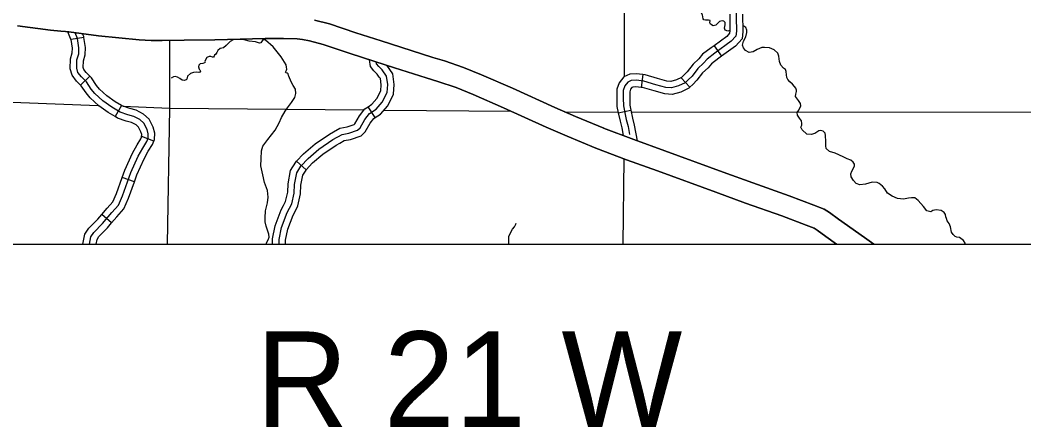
# Model space of a CAD drawing. Extents: x 1373862 to 1377080, y 1164775 to 1170415.
# Drawn here: x 1374841.3 to 1375030.3, y 1168559.4 to 1168636.1 of the extents above; entities that cross this region are included whole.
import ezdxf

# ---------------------------------------------------------------- set-up
doc = ezdxf.new("R2010")
doc.units = 0
for name, color, linetype in [('1', 7, 'Continuous'), ('Default', 7, 'Continuous'), ('Level 10', 7, 'Continuous'), ('Level 32', 7, 'Continuous'), ('Level 35', 7, 'Continuous'), ('Level 45', 7, 'Continuous'), ('Level 46', 7, 'Continuous'), ('Level 5', 7, 'Continuous')]:
    doc.layers.add(name, color=color, linetype=linetype)

msp = doc.modelspace()

# ---------------------------------------------------------------- linework, layer by layer
at = {"layer": '1'}
msp.add_lwpolyline([(1376107.39, 1169553.54), (1374750.71, 1169553.54), (1374750.71, 1168593.87), (1376107.39, 1168593.87)], close=True, dxfattribs=at)
at = {"layer": 'Level 10'}
msp.add_line((1374951.22, 1168615.68), (1374951.16, 1168615.71), dxfattribs=at)
for points in [[(1374896.71, 1168636.09), (1374899.53, 1168635.35), (1374904.52, 1168633.67), (1374909.28, 1168632.15), (1374913, 1168630.97), (1374918.97, 1168629.05), (1374921.19, 1168628.38), (1374924.8, 1168627.15), (1374928.16, 1168625.79), (1374933.97, 1168623.26), (1374942, 1168619.58), (1374945.85, 1168617.93), (1374951.22, 1168615.68)], [(1374951.22, 1168615.68), (1374945.85, 1168617.93), (1374942, 1168619.58), (1374933.97, 1168623.26), (1374928.16, 1168625.79), (1374924.8, 1168627.15), (1374921.19, 1168628.38), (1374918.97, 1168629.05), (1374913, 1168630.97), (1374909.28, 1168632.15), (1374904.52, 1168633.67), (1374899.53, 1168635.35), (1374896.71, 1168636.09)], [(1374840.77, 1168634.97), (1374847.01, 1168634.21), (1374848.95, 1168633.99), (1374849.82, 1168633.93), (1374850.48, 1168633.85), (1374856.06, 1168633.13), (1374863.72, 1168632.39), (1374865.96, 1168632.23), (1374868.02, 1168632.21), (1374872.17, 1168632.28), (1374877.94, 1168632.37), (1374887.42, 1168632.59), (1374890.86, 1168632.61), (1374893.46, 1168632.57), (1374894.46, 1168632.44), (1374895.77, 1168632.15), (1374898.37, 1168631.47), (1374903.26, 1168629.82), (1374908.05, 1168628.29), (1374911.77, 1168627.11), (1374917.77, 1168625.18), (1374919.95, 1168624.52), (1374923.39, 1168623.35), (1374926.59, 1168622.05), (1374932.32, 1168619.56), (1374940.36, 1168615.87), (1374944.27, 1168614.2), (1374949.66, 1168611.94)], [(1374840.77, 1168634.97), (1374847.01, 1168634.21), (1374848.95, 1168633.99), (1374849.82, 1168633.93), (1374850.48, 1168633.85), (1374856.06, 1168633.13), (1374863.72, 1168632.39), (1374865.96, 1168632.23), (1374868.02, 1168632.21), (1374872.17, 1168632.28), (1374877.94, 1168632.37), (1374887.42, 1168632.59), (1374890.86, 1168632.61), (1374893.46, 1168632.57), (1374894.46, 1168632.44), (1374895.77, 1168632.15), (1374898.37, 1168631.47), (1374903.26, 1168629.82), (1374908.05, 1168628.29), (1374911.77, 1168627.11), (1374917.77, 1168625.18), (1374919.95, 1168624.52), (1374923.39, 1168623.35), (1374926.59, 1168622.05), (1374932.32, 1168619.56), (1374940.36, 1168615.87), (1374944.27, 1168614.2), (1374949.66, 1168611.94)], [(1374949.66, 1168611.94), (1374944.27, 1168614.2), (1374940.36, 1168615.87), (1374932.32, 1168619.56), (1374926.59, 1168622.05), (1374923.39, 1168623.35), (1374919.95, 1168624.52), (1374917.77, 1168625.18), (1374911.77, 1168627.11), (1374908.05, 1168628.29), (1374903.26, 1168629.82), (1374898.37, 1168631.47), (1374895.77, 1168632.15), (1374894.46, 1168632.44), (1374893.46, 1168632.57), (1374890.86, 1168632.61), (1374887.42, 1168632.59), (1374877.94, 1168632.37), (1374872.17, 1168632.28), (1374868.02, 1168632.21), (1374865.96, 1168632.23), (1374863.72, 1168632.39), (1374856.06, 1168633.13), (1374850.48, 1168633.85), (1374849.82, 1168633.93), (1374848.95, 1168633.99), (1374847.01, 1168634.21), (1374840.77, 1168634.97)], [(1374951.16, 1168615.71), (1374956.85, 1168613.56), (1374962.69, 1168611.45), (1374973.67, 1168607.43), (1374979.22, 1168605.38), (1374986.09, 1168602.98), (1374990.76, 1168601.19), (1374992.7, 1168600.45), (1374993.68, 1168599.79), (1374995.37, 1168598.56), (1375000.27, 1168595.1), (1375002.01, 1168593.87)], [(1375002.01, 1168593.87), (1375000.27, 1168595.1), (1374995.37, 1168598.56), (1374993.68, 1168599.79), (1374992.7, 1168600.45), (1374990.76, 1168601.19), (1374986.09, 1168602.98), (1374979.22, 1168605.38), (1374973.67, 1168607.43), (1374962.69, 1168611.45), (1374956.85, 1168613.56), (1374951.16, 1168615.71)], [(1374949.66, 1168611.94), (1374955.44, 1168609.76), (1374961.3, 1168607.65), (1374972.27, 1168603.63), (1374977.85, 1168601.57), (1374984.7, 1168599.18), (1374989.3, 1168597.41), (1374990.82, 1168596.83), (1374991.35, 1168596.47), (1374993.02, 1168595.27), (1374995, 1168593.87)], [(1374949.66, 1168611.94), (1374955.44, 1168609.76), (1374961.3, 1168607.65), (1374972.27, 1168603.63), (1374977.85, 1168601.57), (1374984.7, 1168599.18), (1374989.3, 1168597.41), (1374990.82, 1168596.83), (1374991.35, 1168596.47), (1374993.02, 1168595.27), (1374995, 1168593.87)], [(1374995, 1168593.87), (1374993.02, 1168595.27), (1374991.35, 1168596.47), (1374990.82, 1168596.83), (1374989.3, 1168597.41), (1374984.7, 1168599.18), (1374977.85, 1168601.57), (1374972.27, 1168603.63), (1374961.3, 1168607.65), (1374955.44, 1168609.76), (1374949.66, 1168611.94)]]:
    msp.add_lwpolyline(points, dxfattribs=at)
at = {"layer": 'Level 32'}
for p, q in [((1374853.31, 1168632.78), (1374850.91, 1168632.44)), ((1374971.95, 1168631.25), (1374973.38, 1168629.28)), ((1374854.41, 1168625.5), (1374852.66, 1168623.82)), ((1374958.56, 1168625.8), (1374958.25, 1168623.39)), ((1374965.74, 1168625.21), (1374967.4, 1168623.44)), ((1374860.38, 1168620), (1374859.16, 1168617.9)), ((1374953.91, 1168618.61), (1374956.29, 1168619.11)), ((1374866.46, 1168613.27), (1374864.2, 1168614.15)), ((1374862.8, 1168605.6), (1374860.51, 1168606.42)), ((1374858.51, 1168597.85), (1374856.66, 1168599.41))]:
    msp.add_line(p, q, dxfattribs=at)
for points in [[(1374974.81, 1168646.46), (1374975.03, 1168644.83), (1374975.54, 1168642.91), (1374975.94, 1168641.86), (1374975.97, 1168641.25), (1374976.08, 1168639.22), (1374976.15, 1168634.01), (1374976.05, 1168633.07), (1374975.18, 1168632.1), (1374972.11, 1168629.86), (1374970.63, 1168628.74), (1374969.94, 1168627.94), (1374968.89, 1168626.96)], [(1374974.89, 1168637.19), (1374974.94, 1168634.08), (1374974.88, 1168633.59), (1374974.36, 1168633), (1374971.95, 1168631.25)], [(1374977.32, 1168637.22), (1374977.37, 1168633.95), (1374977.21, 1168632.55), (1374976, 1168631.19), (1374973.38, 1168629.28)], [(1374850.92, 1168632.31), (1374850.29, 1168633.87)], [(1374852.66, 1168623.82), (1374851.91, 1168624.6), (1374851.07, 1168625.67), (1374850.74, 1168626.87), (1374850.79, 1168628.75), (1374851.11, 1168629.91), (1374851.14, 1168630.8), (1374850.91, 1168632.44)], [(1374853.31, 1168632.78), (1374853.29, 1168632.96), (1374853.06, 1168633.52)], [(1374854.41, 1168625.5), (1374853.74, 1168626.2), (1374853.29, 1168626.78), (1374853.18, 1168627.17), (1374853.21, 1168628.39), (1374853.53, 1168629.53), (1374853.58, 1168630.94), (1374853.31, 1168632.78)], [(1374971.95, 1168631.25), (1374971.38, 1168630.83), (1374969.79, 1168629.63), (1374969.06, 1168628.78), (1374967.99, 1168627.78), (1374966.89, 1168626.34), (1374966.24, 1168625.69), (1374965.74, 1168625.21)], [(1374973.38, 1168629.28), (1374972.83, 1168628.88), (1374971.46, 1168627.84), (1374970.82, 1168627.1), (1374969.8, 1168626.15), (1374968.73, 1168624.74), (1374967.93, 1168623.94), (1374967.4, 1168623.44)], [(1374968.89, 1168626.96), (1374967.81, 1168625.54), (1374967.09, 1168624.81), (1374966.51, 1168624.27), (1374965.28, 1168623.66), (1374963.94, 1168623.29), (1374962.86, 1168623.37), (1374960.98, 1168623.91), (1374958.71, 1168624.56), (1374957.26, 1168624.74), (1374956.36, 1168624.67), (1374955.71, 1168624.38), (1374955.17, 1168623.66), (1374954.84, 1168622.82), (1374954.84, 1168621.38), (1374954.88, 1168619.93), (1374955.42, 1168617.33), (1374955.75, 1168616.03), (1374956.03, 1168614.51)], [(1374860.38, 1168620), (1374859.21, 1168620.68), (1374857.62, 1168621.83), (1374856.23, 1168623.09), (1374855.67, 1168623.78), (1374854.71, 1168625.2), (1374854.41, 1168625.5)], [(1374958.56, 1168625.8), (1374957.29, 1168625.96), (1374956.06, 1168625.86), (1374954.93, 1168625.36), (1374954.1, 1168624.25), (1374953.63, 1168623.05), (1374953.63, 1168621.36), (1374953.67, 1168619.79), (1374953.91, 1168618.61)], [(1374965.81, 1168625.28), (1374964.85, 1168624.8), (1374963.82, 1168624.52), (1374963.07, 1168624.57), (1374961.32, 1168625.08), (1374958.95, 1168625.75), (1374958.56, 1168625.8)], [(1374859.16, 1168617.9), (1374857.88, 1168618.64), (1374856.09, 1168619.94), (1374854.46, 1168621.42), (1374853.72, 1168622.34), (1374852.81, 1168623.66), (1374852.66, 1168623.82)], [(1374958.25, 1168623.39), (1374957.24, 1168623.52), (1374956.66, 1168623.47), (1374956.49, 1168623.4), (1374956.24, 1168623.06), (1374956.06, 1168622.59), (1374956.06, 1168621.39), (1374956.09, 1168620.07), (1374956.29, 1168619.11)], [(1374967.4, 1168623.44), (1374967.21, 1168623.26), (1374965.72, 1168622.51), (1374964.07, 1168622.07), (1374962.65, 1168622.16), (1374960.65, 1168622.74), (1374958.46, 1168623.37), (1374958.25, 1168623.39)], [(1374866.46, 1168613.27), (1374866.58, 1168613.58), (1374866.63, 1168614.74), (1374866.34, 1168615.92), (1374865.56, 1168617.43), (1374864.53, 1168618.36), (1374863.15, 1168619.08), (1374861.95, 1168619.39), (1374860.67, 1168619.83), (1374860.38, 1168620)], [(1374956.29, 1168619.11), (1374956.6, 1168617.6), (1374956.93, 1168616.29), (1374957.5, 1168613.33)], [(1374864.17, 1168614.08), (1374864.19, 1168614.5), (1374864.05, 1168615.05), (1374863.61, 1168615.92), (1374863.13, 1168616.35), (1374862.28, 1168616.79), (1374861.25, 1168617.06), (1374859.65, 1168617.62), (1374859.16, 1168617.9)], [(1374953.91, 1168618.61), (1374954.24, 1168617.06), (1374954.56, 1168615.77), (1374954.83, 1168614.32)], [(1374860.51, 1168606.42), (1374861.01, 1168607.82), (1374862.46, 1168610.99), (1374863.32, 1168612.57), (1374864.03, 1168613.73), (1374864.2, 1168614.15)], [(1374862.8, 1168605.6), (1374863.27, 1168606.91), (1374864.63, 1168609.9), (1374865.42, 1168611.35), (1374866.22, 1168612.64), (1374866.46, 1168613.27)], [(1374856.66, 1168599.41), (1374857.66, 1168600.6), (1374858.76, 1168601.84), (1374859.43, 1168603.38), (1374860.51, 1168606.42)], [(1374858.51, 1168597.85), (1374859.5, 1168599.01), (1374860.84, 1168600.51), (1374861.69, 1168602.5), (1374862.8, 1168605.6)], [(1374853.12, 1168593.87), (1374853.48, 1168595.72), (1374854.26, 1168596.84), (1374855.92, 1168598.54), (1374856.66, 1168599.41)], [(1374855.59, 1168593.87), (1374855.77, 1168594.75), (1374856.14, 1168595.29), (1374857.72, 1168596.9), (1374858.51, 1168597.85)]]:
    msp.add_lwpolyline(points, dxfattribs=at)
at = {"layer": 'Level 35'}
for points in [[(1374971.16, 1168635.55), (1374971.19, 1168635.99), (1374970.93, 1168636.08), (1374970.35, 1168636.08), (1374970.05, 1168636.12), (1374969.9, 1168636.32), (1374969.85, 1168636.68), (1374969.75, 1168637.07), (1374969.51, 1168637.54), (1374969.23, 1168637.78), (1374968.76, 1168637.78), (1374968.48, 1168637.8), (1374968.22, 1168638.19), (1374967.98, 1168638.77), (1374967.6, 1168639.12), (1374967.12, 1168639.44), (1374966.69, 1168639.7), (1374966.24, 1168639.59), (1374966.05, 1168639.74), (1374965.98, 1168640.09), (1374966.11, 1168640.45), (1374966.22, 1168640.73), (1374966.05, 1168641.01), (1374965.77, 1168641.21)], [(1374974.94, 1168634.09), (1374974.56, 1168634.02), (1374974.04, 1168634.19), (1374973.92, 1168634.58), (1374974.02, 1168635.2), (1374974.02, 1168635.61), (1374973.79, 1168635.89), (1374973.46, 1168635.96), (1374972.95, 1168635.8), (1374972.28, 1168635.14), (1374971.76, 1168635.01), (1374971.31, 1168635.31), (1374971.16, 1168635.55)], [(1374979.29, 1168630.09), (1374978.54, 1168629.99), (1374977.9, 1168630.34), (1374977.49, 1168630.83), (1374977.31, 1168631.37), (1374977.51, 1168632.1), (1374977.96, 1168632.9), (1374978.11, 1168633.72), (1374978.11, 1168634.19), (1374977.92, 1168634.66), (1374977.35, 1168635.07)], [(1374891.46, 1168627.2), (1374891.37, 1168627.65), (1374890.42, 1168629.18), (1374888.92, 1168631.05), (1374887.47, 1168632.28), (1374887.23, 1168632.38), (1374887, 1168632.35), (1374886.6, 1168631.81), (1374886.36, 1168631.71), (1374885.58, 1168631.96), (1374884.39, 1168632.14), (1374883.5, 1168632.38), (1374882.66, 1168632.44), (1374881.43, 1168632.34), (1374880.86, 1168632.07)], [(1374887.05, 1168632.58), (1374887, 1168632.35)], [(1374880.86, 1168632.07), (1374880.09, 1168631.3), (1374879.6, 1168630.84), (1374878.98, 1168630.7), (1374878.5, 1168630.36), (1374878.36, 1168629.95), (1374878.16, 1168629.63), (1374877.87, 1168629.45), (1374877.81, 1168629.27), (1374877.71, 1168629.09), (1374877.51, 1168629.09), (1374877.23, 1168629.23), (1374876.87, 1168629.23), (1374876.47, 1168629.01), (1374876.2, 1168628.6), (1374876.08, 1168628.28), (1374876.12, 1168628.16), (1374876.02, 1168628), (1374875.7, 1168627.92), (1374875.22, 1168627.82), (1374874.96, 1168627.6), (1374874.88, 1168627.26), (1374874.98, 1168626.81), (1374875.1, 1168626.71), (1374875.24, 1168626.47), (1374875.12, 1168626.25), (1374874.94, 1168626.23), (1374874.53, 1168626.27), (1374873.95, 1168626.19), (1374873.37, 1168626.03), (1374872.78, 1168625.5)], [(1374987.29, 1168621.68), (1374987.32, 1168622.14), (1374987.45, 1168622.62), (1374987.47, 1168622.88), (1374987.32, 1168623.24), (1374987.12, 1168623.57), (1374986.69, 1168624.02), (1374986.24, 1168624.47), (1374985.87, 1168624.86), (1374985.66, 1168625.25), (1374985.59, 1168625.78), (1374985.53, 1168626.41), (1374985.38, 1168626.8), (1374985.01, 1168627.05), (1374984.52, 1168627.57), (1374984.3, 1168628.26), (1374984.13, 1168629.31), (1374983.98, 1168629.85), (1374983.29, 1168630.46), (1374982.41, 1168630.84), (1374981.44, 1168630.93), (1374980.93, 1168630.89), (1374980.04, 1168630.54), (1374979.29, 1168630.09)], [(1374891.82, 1168625.62), (1374891.76, 1168625.96), (1374891.56, 1168626.08), (1374891.36, 1168626.14), (1374891.24, 1168626.26), (1374891.3, 1168626.42), (1374891.46, 1168626.64), (1374891.52, 1168626.84), (1374891.46, 1168627.2)], [(1374872.78, 1168625.5), (1374872.68, 1168624.97), (1374872.58, 1168624.83), (1374872.18, 1168624.71), (1374871.82, 1168624.75), (1374871.35, 1168625.05), (1374870.91, 1168625.35), (1374870.47, 1168625.43), (1374870.19, 1168625.41), (1374869.72, 1168625.11)], [(1374893.04, 1168621.47), (1374893.22, 1168622.25), (1374893.12, 1168623.09), (1374892.68, 1168623.78), (1374892.32, 1168624.42), (1374891.87, 1168625.51), (1374891.82, 1168625.62)], [(1374889.32, 1168615.34), (1374890.04, 1168616.74), (1374890.51, 1168617.73), (1374891.17, 1168618.92), (1374891.65, 1168619.56), (1374892.4, 1168620.53), (1374893.04, 1168621.47)], [(1374993.68, 1168611.32), (1374993.08, 1168611.89), (1374992.99, 1168612.38), (1374992.97, 1168613.2), (1374992.95, 1168614.34), (1374992.84, 1168614.79), (1374992.5, 1168615.12), (1374992.07, 1168615.25), (1374991.66, 1168615.2), (1374990.93, 1168614.73), (1374990.22, 1168614.51), (1374989.42, 1168614.6), (1374988.54, 1168615.42), (1374988.3, 1168615.87), (1374988.48, 1168616.28), (1374988.5, 1168616.62), (1374988.39, 1168617.1), (1374988.02, 1168617.57), (1374987.68, 1168618.13), (1374987.62, 1168618.67), (1374987.92, 1168619.1), (1374988.26, 1168619.94), (1374988.24, 1168620.37), (1374987.87, 1168620.95), (1374987.44, 1168621.43), (1374987.29, 1168621.68)], [(1374886.96, 1168606.91), (1374886.64, 1168608.63), (1374886.66, 1168609.9), (1374886.72, 1168611.41), (1374887, 1168612.3), (1374887.95, 1168613.56), (1374889.32, 1168615.34)], [(1375005.51, 1168602.9), (1375004.61, 1168603.48), (1375004.11, 1168604.28), (1375003.66, 1168604.79), (1375003.06, 1168605.29), (1375002.63, 1168605.46), (1375001.74, 1168605.52), (1375000.45, 1168605.14), (1374999.4, 1168605.01), (1374998.69, 1168605.29), (1374998.2, 1168605.85), (1374997.76, 1168606.54), (1374997.68, 1168607.12), (1374997.89, 1168607.59), (1374998.13, 1168608.06), (1374998.37, 1168608.62), (1374998.39, 1168608.9), (1374998.17, 1168609.29), (1374997.68, 1168609.66), (1374996.99, 1168609.92), (1374996.41, 1168610.26), (1374995.42, 1168610.67), (1374994.77, 1168611.01), (1374993.68, 1168611.32)], [(1374887.63, 1168597.26), (1374887.43, 1168598.07), (1374887.43, 1168598.79), (1374887.47, 1168600.12), (1374887.85, 1168601.61), (1374887.97, 1168602.68), (1374887.85, 1168603.99), (1374887.33, 1168605.44), (1374886.96, 1168606.91)], [(1375013.16, 1168600.16), (1375012.78, 1168599.95), (1375012.02, 1168600.12), (1375011.36, 1168600.92), (1375010.41, 1168602.1), (1375009.72, 1168602.58), (1375009.12, 1168602.58), (1375008.58, 1168602.51), (1375007.63, 1168602.34), (1375006.49, 1168602.43), (1375005.51, 1168602.9)], [(1375019.25, 1168593.87), (1375019.2, 1168594.02), (1375018.9, 1168594.51), (1375018.67, 1168594.75), (1375018.17, 1168595.07), (1375017.63, 1168595.16), (1375017.33, 1168595.27), (1375016.97, 1168595.66), (1375016.67, 1168596.09), (1375016.49, 1168597.14), (1375016.24, 1168597.74), (1375015.83, 1168598.26), (1375015.7, 1168598.67), (1375015.61, 1168599.01), (1375015.55, 1168599.42), (1375015.29, 1168599.83), (1375014.69, 1168600.18), (1375013.74, 1168600.29), (1375013.16, 1168600.16)], [(1374887.69, 1168593.87), (1374887.69, 1168594.1), (1374888.01, 1168594.66), (1374888.21, 1168595.16), (1374888.15, 1168595.75), (1374887.63, 1168597.26)], [(1374933.31, 1168593.87), (1374933.32, 1168593.91), (1374933.28, 1168594.59), (1374933.32, 1168595.3), (1374933.66, 1168596.12), (1374933.98, 1168596.65), (1374934.4, 1168597.11), (1374934.65, 1168597.59), (1374934.66, 1168597.8)]]:
    msp.add_lwpolyline(points, dxfattribs=at)
at = {"layer": 'Level 45'}
for p, q in [((1374908.14, 1168617.71), (1374906.83, 1168619.76)), ((1374895.17, 1168607.84), (1374893.36, 1168609.46))]:
    msp.add_line(p, q, dxfattribs=at)
for points in [[(1374854.36, 1168593.87), (1374854.62, 1168595.24), (1374855.2, 1168596.06), (1374856.82, 1168597.72), (1374858.58, 1168599.81), (1374859.8, 1168601.18), (1374860.56, 1168602.94), (1374862.14, 1168607.37), (1374863.54, 1168610.45), (1374864.37, 1168611.96), (1374865.12, 1168613.18), (1374865.38, 1168613.83), (1374865.41, 1168614.62), (1374865.2, 1168615.49), (1374864.59, 1168616.67), (1374863.83, 1168617.36), (1374862.72, 1168617.93), (1374861.6, 1168618.22), (1374860.16, 1168618.73), (1374858.54, 1168619.66), (1374856.85, 1168620.89), (1374855.34, 1168622.25), (1374854.7, 1168623.06), (1374853.76, 1168624.43), (1374852.83, 1168625.4), (1374852.18, 1168626.23), (1374851.96, 1168627.02), (1374852, 1168628.57), (1374852.32, 1168629.72), (1374852.36, 1168630.87), (1374852.11, 1168632.64), (1374851.67, 1168633.69)], [(1374908.91, 1168625.35), (1374908.52, 1168625.92), (1374907.9, 1168626.54), (1374907.26, 1168627.35), (1374907.07, 1168628.6)], [(1374908.14, 1168617.71), (1374909.15, 1168618.36), (1374910.51, 1168619.94), (1374911.59, 1168622.09), (1374911.72, 1168623.97), (1374911.45, 1168625.97), (1374910.91, 1168626.74)], [(1374910.91, 1168626.74), (1374910.34, 1168627.56)], [(1374906.83, 1168619.76), (1374907.54, 1168620.21), (1374908.47, 1168621.29), (1374909.2, 1168622.74), (1374909.28, 1168623.89), (1374909.12, 1168625.06), (1374908.91, 1168625.35)], [(1374900.31, 1168615.02), (1374901.48, 1168615.68), (1374902.89, 1168615.95), (1374904.16, 1168616.38), (1374904.31, 1168616.54), (1374905.17, 1168618.02), (1374906.22, 1168619.37), (1374906.83, 1168619.76)], [(1374901.51, 1168612.9), (1374902.33, 1168613.37), (1374903.51, 1168613.6), (1374905.48, 1168614.26), (1374906.26, 1168615.04), (1374907.19, 1168616.66), (1374907.88, 1168617.55), (1374908.14, 1168617.71)], [(1374893.36, 1168609.46), (1374894.65, 1168610.89), (1374896.82, 1168612.75), (1374899.54, 1168614.58), (1374900.31, 1168615.02)], [(1374895.17, 1168607.84), (1374896.35, 1168609.15), (1374898.29, 1168610.82), (1374900.82, 1168612.51), (1374901.51, 1168612.9)], [(1374890.9, 1168601.12), (1374891.29, 1168601.87), (1374891.67, 1168603.62), (1374891.74, 1168605.23), (1374892.23, 1168607.74), (1374893.2, 1168609.28), (1374893.36, 1168609.46)], [(1374893.06, 1168600), (1374893.6, 1168601.04), (1374894.09, 1168603.31), (1374894.16, 1168604.94), (1374894.53, 1168606.83), (1374895.15, 1168607.81), (1374895.17, 1168607.84)], [(1374888.82, 1168593.87), (1374888.82, 1168594.88), (1374889.33, 1168597.33), (1374890.47, 1168600.3), (1374890.9, 1168601.12)], [(1374891.25, 1168593.87), (1374891.25, 1168594.62), (1374891.67, 1168596.64), (1374892.69, 1168599.3), (1374893.06, 1168600)]]:
    msp.add_lwpolyline(points, dxfattribs=at)
at = {"layer": 'Level 46'}
for points in [[(1374903.2, 1168614.77), (1374904.82, 1168615.32), (1374905.29, 1168615.79), (1374906.18, 1168617.34), (1374907.05, 1168618.46), (1374908.34, 1168619.28), (1374909.49, 1168620.62), (1374910.39, 1168622.42), (1374910.5, 1168623.93), (1374910.28, 1168625.51), (1374909.46, 1168626.7), (1374908.81, 1168627.35), (1374908.41, 1168627.85), (1374908.36, 1168628.19)], [(1374890.04, 1168594.75), (1374890.5, 1168596.99), (1374891.58, 1168599.8), (1374892.45, 1168601.45), (1374892.88, 1168603.47), (1374892.95, 1168605.09), (1374893.38, 1168607.28), (1374894.17, 1168608.54), (1374895.5, 1168610.02), (1374897.55, 1168611.78), (1374900.18, 1168613.55), (1374901.9, 1168614.52), (1374903.2, 1168614.77)], [(1374890.04, 1168593.87), (1374890.04, 1168594.75)]]:
    msp.add_lwpolyline(points, dxfattribs=at)
at = {"layer": 'Level 5'}
for points in [[(1374955.16, 1168683.56), (1374955.04, 1168625.41)], [(1374869.39, 1168632.23), (1374869.4, 1168619.51)], [(1374789.63, 1168622.53), (1374856.01, 1168620.01)], [(1374860.66, 1168619.84), (1374869.4, 1168619.51)], [(1374869.4, 1168619.51), (1374868.98, 1168593.87)], [(1374869.4, 1168619.51), (1374906.06, 1168619.17)], [(1374909.82, 1168619.13), (1374933.74, 1168618.91)], [(1374943.77, 1168618.82), (1374953.89, 1168618.72)], [(1374956.37, 1168618.72), (1375041.33, 1168618.8)], [(1374954.93, 1168609.96), (1374954.75, 1168593.87)]]:
    msp.add_lwpolyline(points, dxfattribs=at)

# ---------------------------------------------------------------- texts
at = {"layer": 'Default'}
msp.add_text('R 21 W', height=18, dxfattribs=at).set_placement((1374885.7, 1168559.39))

doc.saveas('drawing.dxf')
